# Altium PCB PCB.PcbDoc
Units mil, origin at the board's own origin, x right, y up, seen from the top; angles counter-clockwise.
Board outline 1670 x 2400 mil, 2 copper layers (Top Layer, Bottom Layer); 61 components, 44 nets, 256 pads, 85 vias.
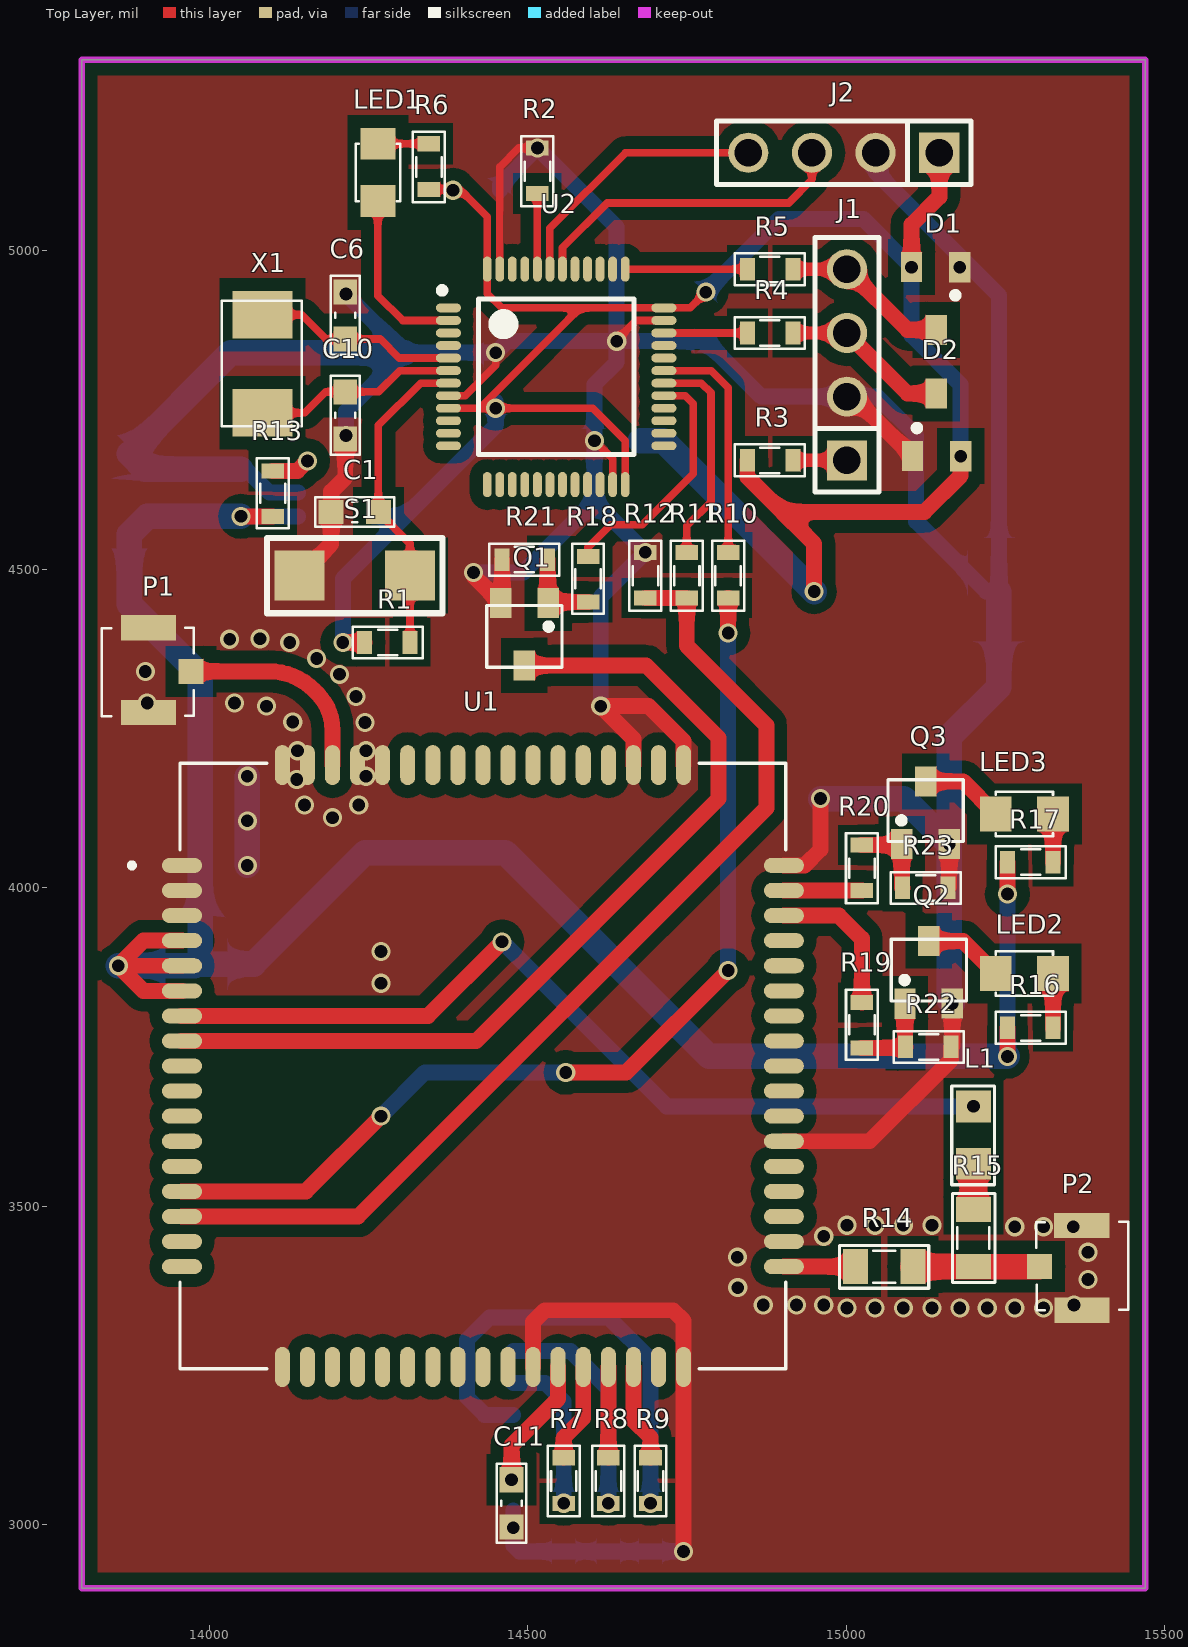
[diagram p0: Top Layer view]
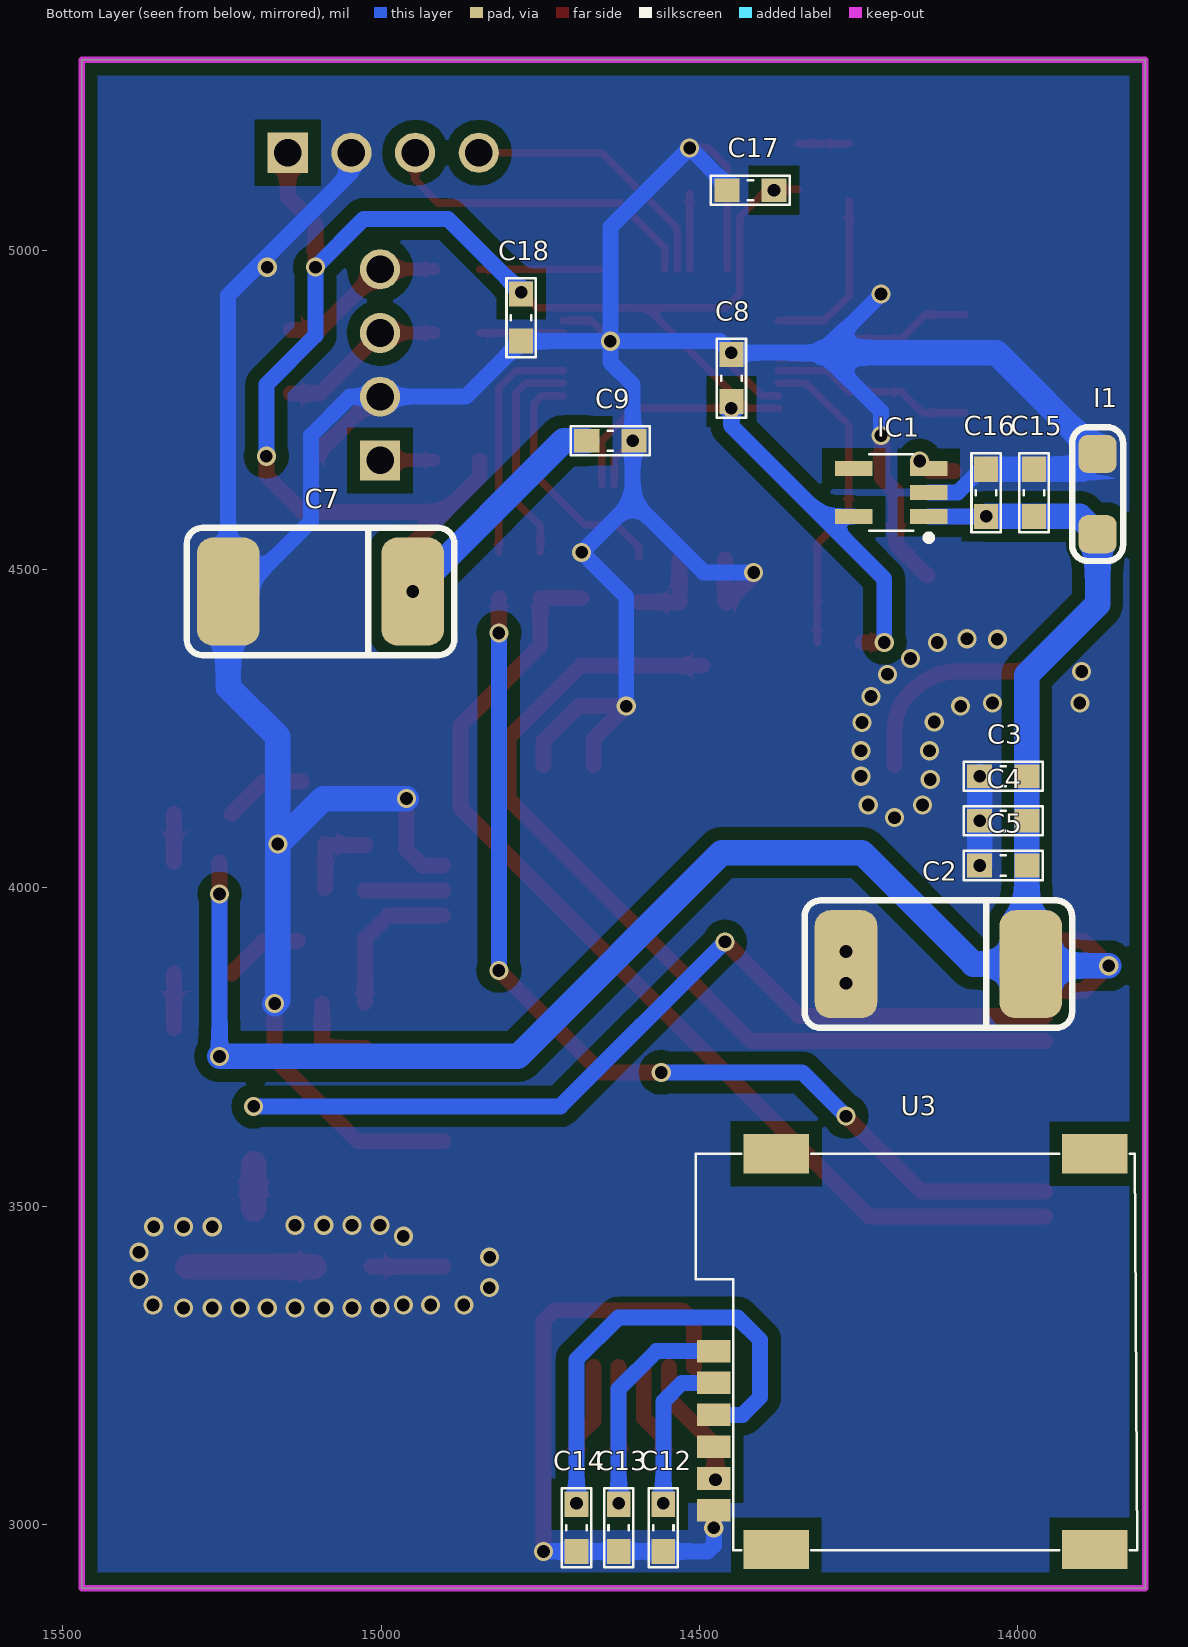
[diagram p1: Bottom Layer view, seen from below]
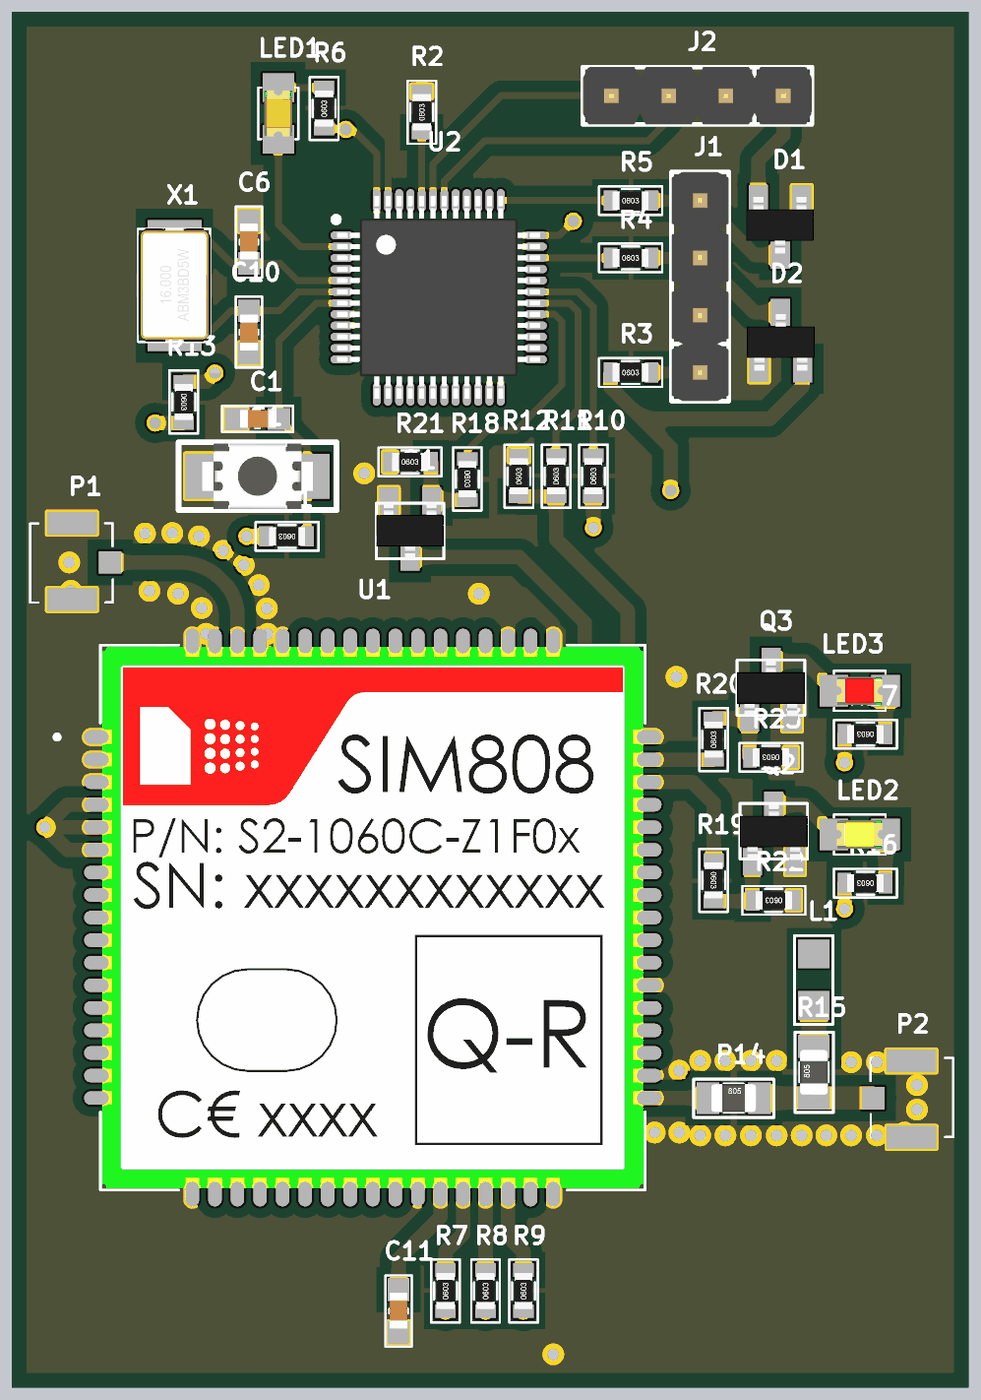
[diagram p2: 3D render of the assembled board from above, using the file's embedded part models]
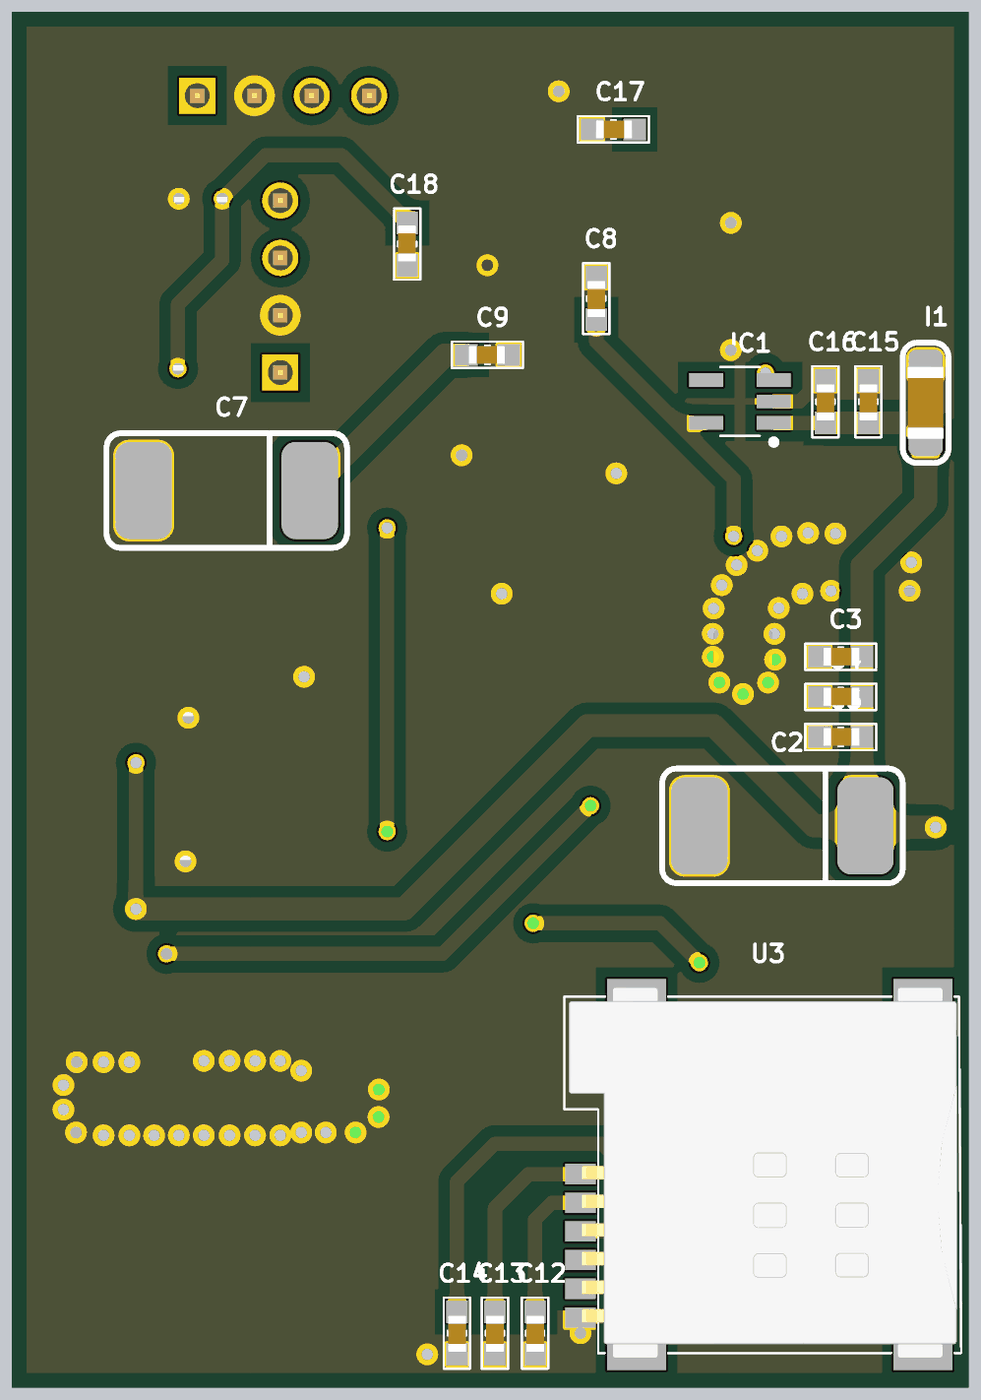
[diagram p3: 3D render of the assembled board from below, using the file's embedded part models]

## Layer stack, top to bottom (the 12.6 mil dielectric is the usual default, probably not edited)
Top Solder: solder mask 0.4, Solder Resist, Dk 3.5
Top Layer: signal copper 1.4
Dielectric 1: dielectric 12.6, FR-4, Dk 4.8
Bottom Layer: signal copper 1.4
Bottom Solder: solder mask 0.4, Solder Resist, Dk 3.5

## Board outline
13800,2900 15470,2900 15470,5300 13800,5300

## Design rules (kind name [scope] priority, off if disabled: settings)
Clearance [All] p1: gap=20 ignorepadtopadclearanceinfootprint=TRUE except(0: Arc-Text Arc-Hole Track-Text Track-Hole SMDPad-Text SMDPad-Hole THPad-Text THPad-Hole Via-Text Via-Hole Fill-Text Fill-Hole Poly-Text Poly-Hole Region-Text Region-Hole Text-Text Text-Hole; 5: Arc-Arc Arc-Track Arc-SMDPad Track-Track Track-SMDPad SMDPad-SMDPad; 10: Arc-THPad Arc-Via Track-THPad Track-Via SMDPad-THPad SMDPad-Via THPad-THPad THPad-Via Via-Via)
PolygonConnect [All] p1: connectstyle=Direct reliefconductorwidth=10 reliefentries=4 polygonreliefangle="90 Angle" airgapwidth=10
RoutingVias [All] p1: holewidth=20 width=30 viastyle="Through Hole" minholewidth=20 minwidth=30 maxholewidth=30 maxwidth=40
SolderMaskExpansion [All] p1: expansion=4
Width [All] p1: maxlimit=40 minlimit=12 preferedwidth=25
30 further rules are at their usual default settings.

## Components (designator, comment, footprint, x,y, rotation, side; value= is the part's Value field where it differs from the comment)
C1 "10uF" CAP_0603 14228.78,4590 r0 top value=33p
C2 "100uF" CAP_7343 14130,3880 r0 bottom
C3 "10uF" CAP_0603 14023.15,4175 r180 bottom value=33p
C4 "100nF" CAP_0603 14023.15,4105 r180 bottom value=33p
C5 "33pF" CAP_0603 14023.15,4035 r180 bottom value=33p
C6 "33pF" CAP_0603 14213.78,4898.52 r90 top value=33p
C7 "100uF" CAP_7343 15100,4465 r0 bottom
C8 "10uF" CAP_0603 14450,4800 r270 bottom value=33p
C9 "100nF" CAP_0603 14640,4701.73 r0 bottom value=33p
C10 "33pF" CAP_0603 14213.78,4741.52 r270 top value=33p
C11 "100nF" CAP_0603 14475,3033.51 r90 top value=33p
C12 "22pF" CAP_0603 14556.85,2995 r270 bottom value=33p
C13 "22pF" CAP_0603 14626.85,2995 r270 bottom value=33p
C14 "22pF" CAP_0603 14693.07,2995 r270 bottom value=33p
C15 "10uF" CAP_0603 13975,4620 r270 bottom value=33p
C16 "100nF" CAP_0603 14050,4620 r270 bottom value=33p
C17 "10uF" CAP_0603 14420,5095 r180 bottom value=33p
C18 "100nF" CAP_0603 14780,4895 r90 bottom value=33p
D1 "DIODE-BAV99" SOT23 15141.69,4925.07 r180 top
D2 "DIODE-BAV99" SOT23 15141.29,4726.65 r0 top
I1 "Batt" CAP_3216 13875,4617.99 r270 bottom value=33p
IC1 "RT9013" SOT23-5 14199.06,4620.4 r0 bottom
J1 "ST_LINK" JP4-D1T 15001.49,4670.9 r90 top
J2 "MPU" JP4-D1T 15146.49,5153.9 r180 top
L1 "47nH" L-0805 15200,3611.69 r270 top value="150 mH"
LED1 "LED" LED-0805-Orange 14265,5168 r270 top value="LED 3 ly Single Colour"
LED2 "LED" LED-0805-Yellow 15325,3865 r180 top value="LED 3 ly Single Colour"
LED3 "LED" LED-0805-Red 15325,4115.59 r180 top value="LED 3 ly Single Colour"
P1 "Antenna" IPXS 13955,4340 r0 top
P2 "Antenna" IPXS 15320,3404.69 r180 top
Q1 "2SC1815" SOT23D 14495,4398 r180 top value=C1815
Q2 "2SC1815" SOT23D 15130,3867 r0 top value=C1815
Q3 "2SC1815" SOT23D 15125,4117.59 r0 top value=C1815
R1 "10k" RES-SMD-0603 14280.39,4385 r180 top
R2 "100k" RES-SMD-0603 14515.47,5125 r90 top
R3 "10R" RES-SMD-0603 14880,4670.9 r0 top
R4 "10R" RES-SMD-0603 14880,4870.9 r0 top
R5 "10R" RES-SMD-0603 14880,4970.9 r0 top
R6 "1k" RES-SMD-0603 14345,5131.52 r90 top
R7 "22R" RES-SMD-0603 14556.85,3068.51 r90 top
R8 "22R" RES-SMD-0603 14626.85,3068.51 r90 top
R9 "22R" RES-SMD-0603 14693.08,3068.51 r90 top
R10 "1k" RES-SMD-0603 14815,4490 r90 top
R11 "1k" RES-SMD-0603 14750,4490 r90 top
R12 "4.7k" RES-SMD-0603 14685,4490 r90 top
R13 "100k" RES-SMD-0603 14100,4619.49 r270 top
R14 "0R" RES-SMD-0805 15060,3405.08 r0 top
R15 "10R" RES-SMD-0805 15200,3450.08 r90 top
R16 "1k" RES-SMD-0603 15290,3780 r180 top
R17 "1k" RES-SMD-0603 15290,4040 r180 top
R18 "4.7k" RES-SMD-0603 14595,4485 r270 top
R19 "4.7k" RES-SMD-0603 15025,3785 r270 top
R20 "4.7k" RES-SMD-0603 15025,4030.59 r90 top
R21 "47k" RES-SMD-0603 14495,4515 r0 top
R22 "47k" RES-SMD-0603 15130,3750 r180 top
R23 "47k" RES-SMD-0603 15125,3999.59 r180 top
S1 "SW-SMD" "SW 3x2x4" 14228.78,4490 r0 top
U1 "SIM808" XCVR_SIM808 14430,3720 r0 top
U2 "STM32" "LQFP 48" 14545,4802 r0 top
U3 "SIM-KF016" "Sim Socket" 14175,3275 r90 bottom value="Sim holder"
X1 "8Mhz" "XTAL 5032 SMD" 14083.78,4823.52 r90 top value=4Mhz

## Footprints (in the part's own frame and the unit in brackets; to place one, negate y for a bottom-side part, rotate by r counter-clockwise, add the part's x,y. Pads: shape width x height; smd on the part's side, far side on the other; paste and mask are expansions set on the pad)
CAP_0603 [mm]
  rect 1x0.95 smd mask+0.076: 1(-0.94,0) 2(0.94,0)
  silkscreen extent -1.57,-0.58 1.57,0.58, body extent -0.77,-0.39 0.83,0.41, height 0.9
CAP_3216 [mil]
  rrect50% 60x60 smd: 1(-62.99,0) 2(62.99,0)
  silkscreen extent -105,-40 105,40, body extent -63,-31 63,31, height 39
CAP_7343 [mm] "Capacitor Tantalum 7343"
  rrect50% 2.5x4.3 smd: 1(-3.81,0) 2(3.556,0)
  silkscreen extent -5.46,-2.54 5.21,2.54, body extent -3.81,-2.29 3.56,2.29, height 3
IPXS [mm] "SOT 23 _ 1-3-2"
  rect 1x1 smd: 1(0.415,-0.01)
  rect 2.2x1 smd: 2(-1.273,-1.658) 3(-1.278,1.73)
  silkscreen extent -3.13,-1.79 0.53,1.73, body extent -2.83,-1.49 0.31,1.56, height 1.55
JP4-D1T [mm] "4 pins, 1 row, straight, gold plating"
  rect 1.6x1.6 hole 1.1: 1(0,0)
  round 1.6 hole 1.1: 2(2.54,0) 3(5.08,0) 4(7.62,0)
  silkscreen extent -1.27,-1.27 8.89,1.27, body extent -1.27,-1.27 8.89,1.27, height 8.54
L-0805 [mil] "Compoment SMD 80x50mil"
  rect 50x55 smd: 1(-45,0) 2(45,0)
  silkscreen extent -77,-34 78,33, body extent -50,-20 50,20, height 43
LED-0805-Orange [mil]
  rect 50x55 smd: 1(0,0) 2(90,0)
  silkscreen extent 0,-35 90,35, body extent 5,-25 85,25, height 43
LED-0805-Red [mil]
  rect 50x55 smd: 1(0,0) 2(90,0)
  silkscreen extent 0,-35 90,35, body extent 5,-25 85,25, height 43
LED-0805-Yellow [mil]
  rect 50x55 smd: 1(0,0) 2(90,0)
  silkscreen extent 0,-35 90,35, body extent 5,-25 85,25, height 43
"LQFP 48" [mm] "LQFP, 48-Leads, Body 7,00x7,00mm, Pitch 0,50mm, IPC Medium Density"
  oval 1x0.35 smd: 1(-4.296,2.75) 2(-4.296,2.25) 3(-4.296,1.75) 4(-4.296,1.25) 5(-4.296,0.75) 6(-4.296,0.25) 7(-4.296,-0.25) 8(-4.296,-0.75) 9(-4.296,-1.25) 10(-4.296,-1.75) 11(-4.296,-2.25) 12(-4.296,-2.75) 25(4.296,-2.75) 26(4.296,-2.25) 27(4.296,-1.75) 28(4.296,-1.25) 29(4.296,-0.75) 30(4.296,-0.25) 31(4.296,0.25) 32(4.296,0.75) 33(4.296,1.25) 34(4.296,1.75) 35(4.296,2.25) 36(4.296,2.75)
  oval 0.35x1 smd: 13(-2.75,-4.296) 14(-2.25,-4.296) 15(-1.75,-4.296) 16(-1.25,-4.296) 17(-0.75,-4.296) 18(-0.25,-4.296) 19(0.25,-4.296) 20(0.75,-4.296) 21(1.25,-4.296) 22(1.75,-4.296) 23(2.25,-4.296) 24(2.75,-4.296) 37(2.75,4.296) 38(2.25,4.296) 39(1.75,4.296) 40(1.25,4.296) 41(0.75,4.296) 42(0.25,4.296) 43(-0.25,4.296) 44(-0.75,4.296) 45(-1.25,4.296) 46(-1.75,4.296) 47(-2.25,4.296) 48(-2.75,4.296)
  silkscreen extent -4.67,-3.1 3.1,3.57, body extent -4.5,-4.5 4.5,4.5, height 1.6
RES-SMD-0603 [mm]
  rect 0.6x0.9 smd: 1(-0.889,0) 2(0.927,0)
  silkscreen extent -1.4,-0.64 1.4,0.64, body extent -0.8,-0.4 0.8,0.4, height 0.43
RES-SMD-0805 [mil]
  rect 39.37x55 smd: 1(-45,0) 2(45,0)
  silkscreen extent -70,-34 70,33, body extent -39,-25 39,25, height 31
"Sim Socket" [mm] "Socket Micro Sim 6P Push"
  rect 0.9x1.35 smd: 1(-5.145,7.685) 2(-2.605,7.685) 3(-0.065,7.685) 5(-6.415,7.685) 6(-3.875,7.685) 7(-1.335,7.685)
  rect 1.56x2.61 smd: ""(-7.975,-7.5) ""(-7.975,5.2) ""(7.805,-7.5) ""(7.805,5.2)
  silkscreen extent -8,-9.2 7.8,8.4, body extent -8.2,-9 8.2,8.2, height 1.35
SOT23 [mm] "SOT 23 _ 1-3-2"
  rect 0.85x1.2 smd: 1(-0.94,-1.245) 2(0.985,-1.25) 3(0.005,1.25)
  silkscreen extent -0.89,-0.25 -0.64,0, body extent -1.47,-1.33 1.53,1.17, height 1.06
SOT23-5 [mm] "SOT23, 5-Leads, Body 3.0x3.0mm (max), Pitch 0.95mm, IPC Medium Density"
  rect 1.5x0.6 smd: 1(-1.5,0.95) 2(-1.5,0) 3(-1.5,-0.95) 4(1.5,-0.95) 5(1.5,0.95)
  silkscreen extent -1.62,-1.52 0.87,1.92, body extent -1.75,-1.52 1.75,1.53, height 1.45
SOT23D [mm] "SOT 23C - 1-3-2 - BCE"
  rect 0.85x1.2 smd: 1(-0.95,-1.25) 2(0.94,-1.245) 3(0,1.25)
  silkscreen extent -1.5,-1.14 1.5,1.32, body extent -1.5,-1.17 1.5,1.33, height 1.06
"SW 3x2x4" [mm]
  rect 2x2 smd: 1(-2.2,0) 2(2.2,0)
  silkscreen extent -3.5,-1.5 3.5,1.5, body extent -2.45,-1.45 2.45,1.45, height 2
XCVR_SIM808 [mm]
  oval 1.6x0.6 smd: 1(-12,8) 2(-12,7) 3(-12,6) 4(-12,5) 5(-12,4) 6(-12,3) 7(-12,2) 8(-12,1) 9(-12,0) 10(-12,-1) 11(-12,-2) 12(-12,-3) 13(-12,-4) 14(-12,-5) 15(-12,-6) 16(-12,-7) 17(-12,-8) 35(12,-8) 36(12,-7) 37(12,-6) 38(12,-5) 39(12,-4) 40(12,-3) 41(12,-2) 42(12,-1) 43(12,0) 44(12,1) 45(12,2) 46(12,3) 47(12,4) 48(12,5) 49(12,6) 50(12,7) 51(12,8)
  oval 0.6x1.6 smd: 18(-8,-12) 19(-7,-12) 20(-6,-12) 21(-5,-12) 22(-4,-12) 23(-3,-12) 24(-2,-12) 25(-1,-12) 26(0,-12) 27(1,-12) 28(2,-12) 29(3,-12) 30(4,-12) 31(5,-12) 32(6,-12) 33(7,-12) 34(8,-12) 52(8,12) 53(7,12) 54(6,12) 55(5,12) 56(4,12) 57(3,12) 58(2,12) 59(1,12) 60(0,12) 61(-1,12) 62(-2,12) 63(-3,12) 64(-4,12) 65(-5,12) 66(-6,12) 67(-7,12) 68(-8,12)
  silkscreen extent -14.1,-12.07 12.07,12.07, body extent -12,-12 12,12, height 2.8
"XTAL 5032 SMD" [mm] "SMD 5032 XTAL Footprint"
  rect 1.9x2.4 smd: 1(-1.981,0) 2(1.93,0)
  silkscreen extent -2.51,-1.57 2.49,1.63, body extent -2.5,-1.6 2.5,1.6, height 1.31

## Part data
C1 C3 C4 C5 C6 C8 C9 C10 C11 C12 C13 C14 C15 C16 C17 C18: library part CapSMD, "Capacitor"
C2 C7: library part "Cap Pol", "Tantalum"
D1 D2: "ZENER, SOT23,", Current - Average Rectified (Io) (per Diode)=200mA, Current - Reverse Leakage @ Vr="2.5礎 @ 70V", Manufacturer="ON Semiconductor / Fairchild", Manufacturer Part Number=BAV99, Package / Case="TO-236-3, SC-59, SOT-23-3", Standard Package=1, Supplier Device Package="SOT-23-3 (TO-236)", Supplier Part Number 1=BAV99FSCT-ND, Voltage - DC Reverse (Vr) (Max)=70V, Voltage - Forward (Vf) (Max) @ If="1.25V @ 150mA"
I1: library part CapSMD, "Pad"
IC1: "RT9013-33GB IC REG LINEAR 3.3V 500mA SOT23-5"
J1 J2: library part Header4, "Header IDC, 4 x 1 Pin Vertical 2.54mm Pitch (Non-Boxed, Male)", Manufacturer="Würth Elektronik eiSos GmbH", partNo=613002143121
L1: library part "Inductor Ferit", "Inductor"
LED1 LED2 LED3: "LED Single colour Green and Red"
P1 P2: library part IPXSx66, "Antenna GSM GPS"
Q1 Q2 Q3: "NPN 600mW, ECB"
R1 R2 R3 R4 R5 R6 R7 R8 R9 R10 R11 R12 R13 R14 R15 R16 R17 R18 R19 R20 R21 R22 R23: library part "Resistor - SMD", "Resistor", Manufacturer="Generic Components"
S1: "Switch"
U1: "SIM808 GPS, GPRS/GSM RF Arduino Platform Evaluation Expansion Board", Package=None
U2: library part STM32F103C8T6, "STM32 ARM-based 32-bit MCU with 64 Kbytes Flash, 64-pin LQFP, Industrial Temperature"
U3: library part "Sim holder", "SIM Card Holder KF-016"
X1: library part XT2, "Crystal For all Crystal 2pin."

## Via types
v1: diameter 30, hole 20, Top Layer to Bottom Layer, 85 vias

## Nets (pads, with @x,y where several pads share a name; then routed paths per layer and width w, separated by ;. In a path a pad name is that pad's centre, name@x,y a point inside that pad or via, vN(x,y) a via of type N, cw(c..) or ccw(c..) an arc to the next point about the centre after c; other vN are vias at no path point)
3V3: C7.1 C8.2 C9.2 C17.2 C18.2 D1.2 D2.2 IC1.5 J2.1 R1.2 R3.1 R6.1 U2.9 U2.24 U2.36 U2.48 | length 3627.3
  Top Layer w12: R6.1 14393.49,5096.51 14436.73,5053.27 U2.48 14436.73,4932.79 14459.25,4910.27 14582.48,4910.27 ; U2.9 14425,4752.79 ; U2.24 14653.27,4701.73 14602.21,4752.79 14425,4752.79 ; v1(14780,4935) 14755.27,4910.27 U2.36 14582.48,4910.27 ; 14425,4752.79 14582.48,4910.27
  Top Layer w25: v1(14210,4385) R1.2 ; R3.1 14845,4645 14900,4590 ; v1(14950,4465) 14950,4540 14900,4590 ; v1(15102.89,4974.28) 15102.89,5040.9 15146.49,5084.49 J2.1 ; v1(15180.09,4677.44) 15180.09,4646.87 15123.22,4590 14900,4590
  Bottom Layer w25: v1(14210,4385) 14210,4485 14308,4583 ; IC1.5 14308,4583 ; C8.2 14450,4725 14308,4583 ; v1(14780,4935) 14895,5050 15027.18,5050 v1(15102.89,4974.28) 15102.89,4867.11 15180.09,4789.91 v1(15180.09,4677.44)
  Bottom Layer w40: C9.2 14713.27,4701.73 v1(14950,4465)
  other v1: 14450,4752.79 14383,5095
GND: C1.1 C2.2 C3.1 C4.1 C5.1 C6.2 C7.2 C8.1 C9.1 C10.2 C11.1 C12.2 C13.2 C14.2 C15.1 C16.1 C17.1 C18.1 D1.1 D2.1 I1.1 IC1.2 J1.2 J2.2 P1.2 P1.3 P2.2 P2.3 Q1.2 Q2.2 Q3.2 R2.2 R12.2 R21.1 R22.1 R23.1 S1.1 U1.1 U1.2 U1.3 U1.18 U1.28 U1.34 U1.36 U1.40 U1.51 U1.52 U1.54 U1.64 U1.65 U1.67 U1.68 U2.8 U2.23 U2.35 U2.47 U3.5 | length 8393.5
  Top Layer w12: U2.8 14402.47,4772.47 14450,4820 v1(14450,4840) ; U2.47 14456.42,5131.42 14486.49,5161.49 v1(14515.47,5161.49) ; v1(14605,4701.73) 14633.58,4673.15 U2.23 ; v1(14640,4858) 14640,4860 14670.58,4890.58 U2.35
  Top Layer w25: S1.1 14191.78,4539.61 C1.1 14191.78,4621.78 14213.78,4643.78 C10.2 ; v1(14415,4495) 14415,4490 Q1.2 14460,4449 R21.1 ; U1.28 14508.74,3318.27 14527.07,3336.59 14728.37,3336.59 14744.96,3320 U1.34 14745,3247.52 v1(14745,2958) ; U1.54 14666.22,4233.78 v1(14615,4285) 14690,4285 14744.96,4230.04 U1.52 ; U1.40 15036.89,3601.89 15165,3730 R22.1 15167,3751.99 v1(15167,3818) ; U1.51 14934.96,4034.96 14960,4060 v1(14960,4140) ; J1.2 15011.04,4770.9 D2.1 ; R23.1 15162,4001.59 v1(15162,4068.59)
  Bottom Layer w25: C16.1 14058,4657 14094.6,4620.4 IC1.2 ; v1(14215,4710) 14215,4748 14307,4840 ; v1(14215,4932) 14307,4840 ; v1(14415,4495) 14493.51,4495 14605,4606.49 ; C17.1 14457,5103.02 v1(14515.47,5161.49) 14640,5036.96 v1(14640,4858) ; U3.5 v1(14477.56,2994.94) 14477.56,2967.44 14487,2958 C12.2 C13.2 C14.2 v1(14745,2958) ; v1(14615,4285) 14615,4456.5 v1(14685,4526.49) 14605,4606.49 ; J2.2 15046.49,5123.51 15240,4930 C7.2 15220,4465 15110,4575 15110,4710 15049.1,4770.9 J1.2 14867.1,4770.9 C18.1 v1(14640,4858) ; 14307,4840 v1(14450,4840) 14468,4858 v1(14640,4858) ; 14605,4606.49 v1(14605,4701.73) 14605,4790 14640,4825 v1(14640,4858)
  Bottom Layer w40: C16.1 C15.1 13898.98,4657 I1.1 14034.02,4840 14307,4840 ; v1(14060.15,4035) v1(14060.15,4105) v1(14060.15,4175) ; v1(14960,4140) 15090.59,4140 v1(15162,4068.59) ; v1(15167,3818) 15162,3823 v1(15162,4068.59) ; C7.2 15240,4315 15162,4237 v1(15162,4068.59)
  other v1: 15001.49,3340 15045.57,3340 15090,3340 15135,3340 15178.69,3340 15221.7,3340 15265,3340 15310,3340 14870,3345 14922.13,3345 14965,3345 15358.11,3345 14830,3372.05 15380,3385 14829.47,3420 15380,3427.73 14965,3452.85 15265,3467.74 15310,3467.74 15356.81,3467.74 15001.49,3469.96 15045.57,3469.96 15090,3470 15135,3469.96 14270,3850 14270,3900 14193.78,4110 14149.93,4130 14235,4130 14137.72,4170 14246.46,4175 14138.9,4215 14246.46,4215 14245,4259.24 14131.38,4260 14090,4285 13902.86,4290 14040,4290 14230.84,4300 14204.85,4335 13900,4339.61 14168.88,4360 14126.62,4385 14032.35,4390 14080,4390.86 15178.69,4974.07
GPIO_PWRKEY: R18.1 U2.29 | length 388.4
  Top Layer w12: R18.1 14595,4534.61 14630.39,4570 14680,4570 14760,4650 14760,4760 14747.53,4772.47 U2.29
GPS: R14.1 U1.35 | length 112.6
  Top Layer w25: U1.35 15014.96,3405.04 R14.1
GSM: P1.1 U1.66 | length 327.6
  Top Layer w25: P1.1 14093.97,4339.61 cw(c14093.97,4239.61) 14164.68,4310.32 14170,4305 cw(c14112.59,4247.59) 14193.78,4247.59 U1.66
NetC6_1: C6.1 U2.5 X1.2 | length 320.2
  Top Layer w12: X1.2 14145.48,4899.52 14183.48,4861.52 C6.1 14268.48,4861.52 14298.47,4831.53 U2.5
NetC10_1: C10.1 U2.6 X1.1 | length 319.6
  Top Layer w12: X1.1 14149.93,4745.52 14182.93,4778.52 C10.1 14266.04,4778.52 14299.36,4811.84 U2.6
NetD1_3: D1.3 J1.4 R5.2 | length 264.4
  Top Layer w20: R5.2 J1.4
  Top Layer w25: J1.4 15096.54,4875.86 D1.3
NetD2_3: D2.3 J1.3 R4.2 | length 264.4
  Top Layer w20: R4.2 J1.3
  Top Layer w25: J1.3 15096.53,4775.86 D2.3
NetIC1_3: IC1.3 R13.1 | length 60.8
  Top Layer w25: R13.1 14138.9,4654.49 v1(14154.41,4670)
NetJ1_1: J1.1 R3.2 | length 85
  Top Layer w20: R3.2 J1.1
NetL1_2: L1.2 R15.2 | length 71.6
  Top Layer w40: R15.2 L1.2
NetLED1_1: LED1.1 R6.2 | length 80
  Top Layer w12: LED1.1 R6.2
NetLED1_2: LED1.2 U2.2 | length 275.5
  Top Layer w12: LED1.2 14265,4929.52 14303.94,4890.58 U2.2
NetLED2_1: LED2.1 R16.1 | length 85
  Top Layer w25: R16.1 LED2.1
NetLED2_2: LED2.2 Q2.3 | length 126.2
  Top Layer w25: Q2.3 15183.79,3916.21 LED2.2
NetLED3_1: LED3.1 R17.1 | length 75.6
  Top Layer w25: R17.1 LED3.1
NetLED3_2: LED3.2 Q3.3 | length 131.2
  Top Layer w25: Q3.3 15183.79,4166.81 LED3.2
NETLIGHT: R20.1 U1.50 | length 122.6
  Top Layer w25: U1.50 R20.1
NetP2_1: P2.1 R14.2 R15.1 | length 198.7
  Top Layer w40: R14.2 R15.1 P2.1
NetQ1_1: Q1.1 R18.2 R21.2 | length 131.3
  Top Layer w25: R21.2 14531.49,4448.13 Q1.1 14533.7,4448.51 R18.2
NetQ2_1: Q2.1 R19.2 R22.2 | length 137.3
  Top Layer w25: R19.2 15092.03,3748.51 R22.2 15092.6,3750.91 Q2.1
NetQ3_1: Q3.1 R20.2 R23.2 | length 132.3
  Top Layer w25: R20.2 15086.3,4067.08 Q3.1 15087.6,4000.5 R23.2
NetR2_1: R2.1 U2.44 | length 118.9
  Top Layer w12: U2.44 R2.1
NetR7_2: R7.2 U1.30 | length 155.2
  Top Layer w25: R7.2 14556.85,3136.85 14587.48,3167.48 U1.30
NetR8_2: R8.2 U1.31 | length 142.6
  Top Layer w25: R8.2 U1.31
NetR9_2: R9.2 U1.32 | length 153.7
  Top Layer w25: U1.32 14666.22,3163.78 14693.07,3136.93 R9.2
NRST: C1.2 R1.1 S1.2 U2.7 | length 498.9
  Top Layer w12: R1.1 S1.2 14315.39,4540.39 C1.2 14265.78,4725.78 14332.16,4792.16 U2.7
RX1: R10.2 U2.31 | length 370.5
  Top Layer w12: U2.31 14788.16,4811.84 14815,4785 R10.2
SCL: J2.3 U2.42 | length 511.9
  Top Layer w12: U2.42 14554.84,5004.84 14625,5075 14910,5075 14946.49,5111.49 J2.3
SDA: J2.4 U2.43 | length 424.5
  Top Layer w12: U2.43 14535.16,5035.16 14653.9,5153.9 J2.4
SIM_CLK: C13.1 R8.1 U3.3 | length 353.5
  Bottom Layer w25: U3.3 14567.56,3272.44 14626.85,3213.14 v1(14626.85,3033.51)
SIM_DATA: C12.1 R7.1 U3.7 | length 251.1
  Bottom Layer w25: U3.7 14527.56,3222.44 14556.85,3193.14 v1(14556.85,3033.51)
SIM_PWRKEY: Q1.3 U1.8 | length 1447.2
  Top Layer w25: U1.8 14419.37,3759.37 14800,4140 14800,4235 14686.21,4348.79 Q1.3
SIM_RST: C14.1 R9.1 U3.2 | length 729.6
  Bottom Layer w25: U3.2 14432.56,3172.44 14405,3200 14405,3290 14440,3325 14627.44,3325 14693.08,3259.37 v1(14693.08,3033.51)
SIM_RX: R11.1 R12.1 U1.15 | length 1629.8
  Top Layer w25: U1.15 14233.78,3483.78 14875,4125 14875,4255 14750,4380 R11.1 R12.1
SIM_TX: R10.1 U1.14 | length 1586.1
  Top Layer w25: U1.14 14151.89,3523.15 v1(14270,3641.26) ; v1(14560,3710) 14655,3710 v1(14815,3870) ; v1(14815,4400) R10.1
  Bottom Layer w25: v1(14270,3641.26) 14338.74,3710 v1(14560,3710) ; v1(14815,3870) v1(14815,4400)
SIM_VCC: C11.2 U1.29 U3.1 | length 207.3
  Top Layer w25: v1(14475,3070.51) 14475,3124.53 14548.11,3197.64 U1.29
STATUS: R19.1 U1.49 | length 237.6
  Top Layer w25: U1.49 14988.78,3956.22 15025,3920 R19.1
SWCLK: R5.1 U2.37 | length 191.8
  Top Layer w12: U2.37 14844.76,4971.13 R5.1
SWDIO: R4.1 U2.34 | length 130.9
  Top Layer w12: U2.34 R4.1
TX1: R11.2 U2.30 | length 346.5
  Top Layer w12: U2.30 14772.84,4792.16 14788.16,4776.84 14788.16,4606.16 14750,4568 R11.2
VBAT: C2.1 C3.2 C4.2 C5.2 C15.2 C16.2 I1.2 IC1.1 R13.2 R16.2 R17.2 U1.4 U1.5 U1.6 | length 3335
  Top Layer w25: U1.6 13896.89,3838.11 v1(13857.52,3877.48) ; U1.5 v1(13857.52,3877.48) ; U1.4 13896.89,3916.85 v1(13857.52,3877.48) ; v1(14050,4583) R13.2 ; v1(15253.51,3735) R16.2 ; v1(15253.51,3990) R17.2
  Bottom Layer w25: v1(14050,4583) IC1.1 ; v1(15253.51,3735) v1(15253.51,3990)
  Bottom Layer w40: v1(13857.52,3877.48) 13977.48,3877.48 C2.1 ; v1(14050,4583) C15.2 13903,4583 I1.2 13875,4445 13986.15,4333.85 C3.2 C4.2 C5.2 13986.15,3886.15 C2.1 ; v1(15253.51,3735) 14785,3735 14465,4055 14245,4055 14070,3880 C2.1
VDD_EXT: L1.1 U1.7 | length 1397.6
  Top Layer w25: U1.7 14343.74,3798.74 v1(14460,3915)
  Bottom Layer w25: v1(14460,3915) 14718.31,3656.69 v1(15200,3656.69)
pads on no net: IC1.4 U1.9 U1.10 U1.11 U1.12 U1.13 U1.16 U1.17 U1.19 U1.20 U1.21 U1.22 U1.23 U1.24 U1.25 U1.26 U1.27 U1.33 U1.37 U1.38 U1.39 U1.41 U1.42 U1.43 U1.44 U1.45 U1.46 U1.47 U1.48 U1.53 U1.55 U1.56 U1.57 U1.58 U1.59 U1.60 U1.61 U1.62 U1.63 U2.1 U2.3 U2.4 U2.10 U2.11 U2.12 U2.13 U2.14 U2.15 U2.16 U2.17 U2.18 U2.19 U2.20 U2.21 U2.22 U2.25 U2.26 U2.27 U2.28 U2.32 U2.33 U2.38 U2.39 U2.40 U2.41 U2.45 U2.46 U3. U3.6

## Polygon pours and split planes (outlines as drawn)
GND on Top Layer "GND_L01_P000" (solid, remove dead copper, pour order 0): 13800,2900 15470,2900 15470,5300 13800,5300
GND on Bottom Layer "GND_L02_P002" (solid, remove dead copper, pour order 2): 13800,2900 15470,2900 15470,5300 13800,5300

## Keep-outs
Keep-Out Layer:
  lines w10: 13800,2900 15470,2900 15470,5300 15250,5300 13800,5300 13800,2900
